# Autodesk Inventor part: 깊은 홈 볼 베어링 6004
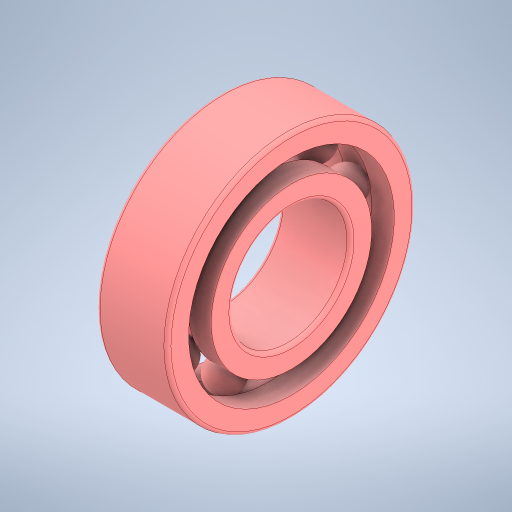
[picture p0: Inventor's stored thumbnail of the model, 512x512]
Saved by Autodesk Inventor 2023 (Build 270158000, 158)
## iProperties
Created: 2026-03
Part Number: 깊은 홈 볼 베어링 6004
Material: 강철, 연강
Description: 깊은 그루브 볼 베어링
Document SubType Name: Modeling
Designer: home
Density: 7.85 g/cm^3
Appearance: 기본값
Author: jhkim
Sending System: Autodesk Inventor 2026
Preprocessor: ST-DEVELOPER v20.1
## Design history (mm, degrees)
feature "Solid1"
feature "Solid1:1"
feature "Solid1:2"
feature "Solid1:3"
feature "Solid1:4"
feature "Solid1:5"
feature "Solid1:6"
feature "Solid1:7"
feature "Solid1:8"
feature "Solid1:9"
feature "Solid1:10"
node "솔리드1"
node "솔리드2"
node "솔리드3"
node "솔리드4"
node "솔리드5"
node "솔리드6"
node "솔리드7"
node "솔리드8"
node "솔리드9"
node "솔리드10"
node "솔리드11"
